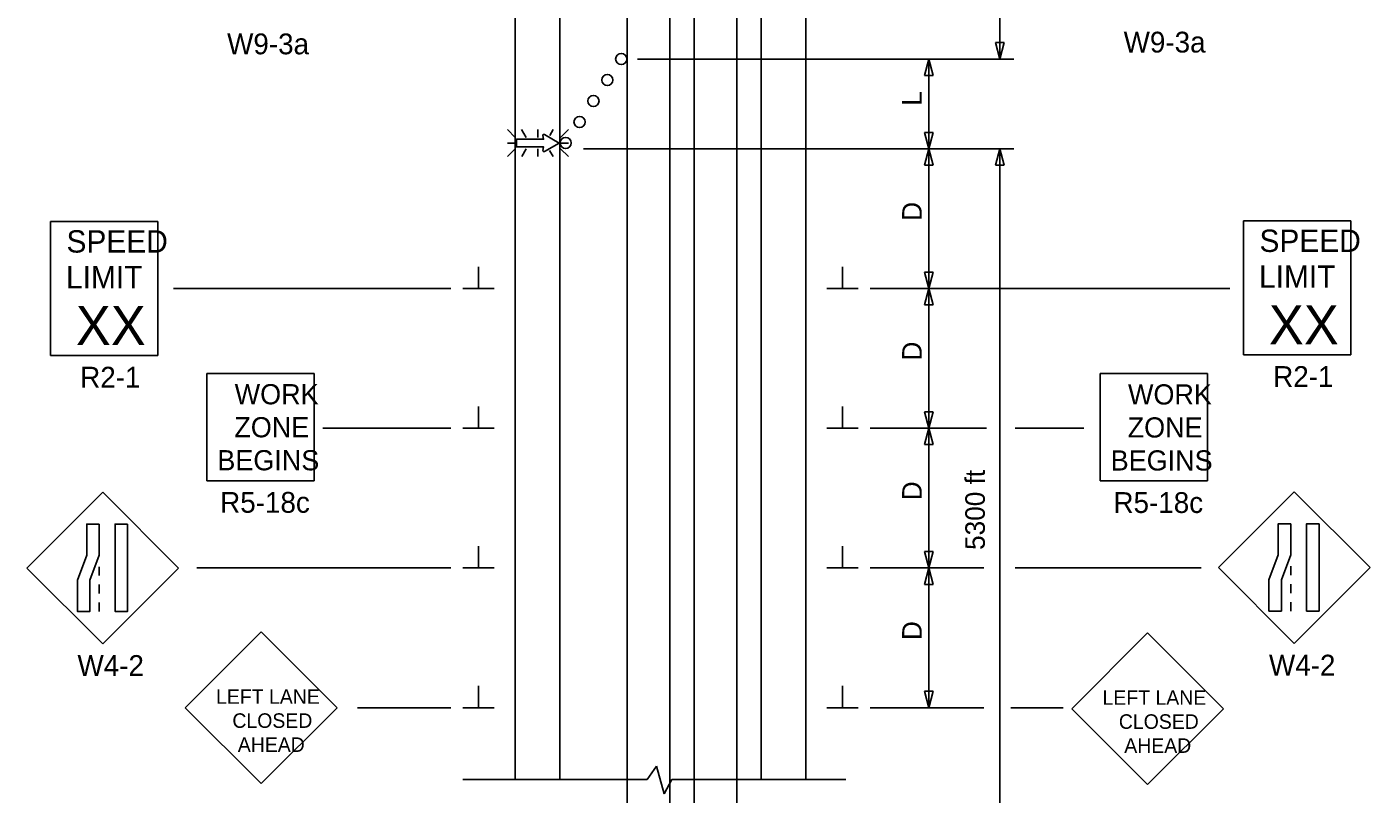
# Model space of a CAD drawing. Extents: x 16450 to 18482, y 7002 to 8333.
# Drawn here: x 16766 to 17246.6, y 7557.2 to 7831.7 of the extents above; entities that cross this region are included whole.
import ezdxf

# ---------------------------------------------------------------- set-up
doc = ezdxf.new("R2010")
doc.units = 0
for name, color, linetype in [('ALI_LEGAL_EX', 7, 'Continuous'), ('PAVT_EDGE_EX', 7, 'Continuous'), ('TRAFFIC_SIGNS_PR', 7, 'Continuous'), ('TYPICAL_TEXT_DIMEN_PR', 7, 'Continuous')]:
    doc.layers.add(name, color=color, linetype=linetype)

msp = doc.modelspace()

# ---------------------------------------------------------------- linework, layer by layer
at = {"layer": 'ALI_LEGAL_EX'}
for p, q in [((16980.68, 8333.08), (16980.68, 7514.94)), ((17004.68, 8333.08), (17004.68, 7514.94)), ((16995.95, 8258.85), (16995.95, 7440.72)), ((17019.95, 8258.85), (17019.95, 7440.72)), ((16980.68, 7589.94), (16980.68, 8211.08)), ((17004.68, 7589.94), (17004.68, 8211.08))]:
    msp.add_line(p, q, dxfattribs=at)
for points in [[(16980.68, 7744.94), (16980.68, 7769.94)], [(17004.68, 7744.94), (17004.68, 7769.94)], [(16980.68, 7612.44), (16980.68, 7637.44)], [(17004.68, 7612.44), (17004.68, 7637.44)]]:
    msp.add_lwpolyline(points, dxfattribs=at)
at = {"layer": 'PAVT_EDGE_EX'}
for p, q in [((16940.68, 8211.52), (16940.68, 7562.44)), ((16956.68, 8211.52), (16956.68, 7562.44)), ((17028.68, 8211.52), (17028.68, 7562.44)), ((17044.68, 8211.52), (17044.68, 7562.44))]:
    msp.add_line(p, q, dxfattribs=at)
at = {"layer": 'TRAFFIC_SIGNS_PR'}
for p, q in [((16940.7, 7792.16), (16937.88, 7794.99)), ((16942.99, 7794.98), (16944.62, 7792.16)), ((16948.78, 7792.16), (16948.78, 7794.98)), ((16954.25, 7794.98), (16953.04, 7792.89)), ((16959.69, 7794.98), (16956.87, 7792.16)), ((16940.7, 7790.13), (16937.88, 7790.13)), ((16940.7, 7788.1), (16937.88, 7785.28)), ((16944.65, 7788.1), (16943.02, 7785.28)), ((16948.78, 7788.1), (16948.78, 7785.28)), ((16952.96, 7787.47), (16954.22, 7785.28)), ((16956.87, 7790.13), (16959.69, 7790.13)), ((16959.69, 7785.28), (16956.87, 7788.1)), ((16774.36, 7762.08), (16812.76, 7762.08)), ((16774.36, 7714.08), (16774.36, 7762.08)), ((16812.76, 7714.08), (16812.76, 7762.08)), ((17201.21, 7762.31), (17239.61, 7762.31)), ((17201.21, 7714.31), (17201.21, 7762.31)), ((17239.61, 7714.31), (17239.61, 7762.31)), ((16774.36, 7714.08), (16812.76, 7714.08)), ((17201.21, 7714.31), (17239.61, 7714.31)), ((16830.31, 7669.29), (16830.31, 7707.69)), ((16830.31, 7707.69), (16868.71, 7707.69)), ((16868.71, 7669.29), (16868.71, 7707.69)), ((17149.93, 7669.22), (17149.93, 7707.62)), ((17149.93, 7707.62), (17188.33, 7707.62)), ((17188.33, 7669.22), (17188.33, 7707.62)), ((16830.31, 7669.29), (16868.71, 7669.29)), ((17149.93, 7669.22), (17188.33, 7669.22)), ((16793.11, 7665.22), (16765.96, 7638.06)), ((16820.26, 7638.06), (16793.11, 7665.22)), ((17219.41, 7665.36), (17192.26, 7638.21)), ((17246.57, 7638.21), (17219.41, 7665.36)), ((16765.96, 7638.06), (16793.11, 7610.91)), ((16791.86, 7638.56), (16791.86, 7635.36)), ((16793.11, 7610.91), (16820.26, 7638.06)), ((17192.26, 7638.21), (17219.41, 7611.05)), ((17218.17, 7638.7), (17218.17, 7635.5)), ((17219.41, 7611.05), (17246.57, 7638.21)), ((16791.86, 7632.16), (16791.86, 7628.96)), ((17218.17, 7632.3), (17218.17, 7629.1)), ((16791.86, 7625.76), (16791.86, 7622.56)), ((17218.17, 7625.9), (17218.17, 7622.7)), ((16849.78, 7615.25), (16822.62, 7588.09)), ((16876.93, 7588.09), (16849.78, 7615.25)), ((17166.95, 7614.9), (17139.79, 7587.74)), ((17194.1, 7587.74), (17166.95, 7614.9)), ((16822.62, 7588.09), (16849.78, 7560.94)), ((16849.78, 7560.94), (16876.93, 7588.09)), ((17139.79, 7587.74), (17166.95, 7560.59)), ((17166.95, 7560.59), (17194.1, 7587.74))]:
    msp.add_line(p, q, dxfattribs=at)
for points in [[(16950.61, 7792.81), (16950.84, 7791.52), (16941.12, 7791.52), (16941.12, 7788.77), (16950.84, 7788.77), (16950.61, 7787.47)], [(16951.11, 7787.12), (16956.42, 7790.13), (16951.11, 7793.17)]]:
    msp.add_lwpolyline(points, dxfattribs=at)
for points in [[(16791.86, 7653.8), (16791.86, 7642.62), (16788.52, 7633.74), (16788.52, 7622.56), (16784.02, 7622.56), (16784.02, 7633.74), (16787.37, 7642.62), (16787.37, 7653.8)], [(16802, 7653.8), (16802, 7622.56), (16797.51, 7622.56), (16797.51, 7653.8)], [(17218.17, 7653.94), (17218.17, 7642.76), (17214.82, 7633.88), (17214.82, 7622.7), (17210.33, 7622.7), (17210.33, 7633.88), (17213.67, 7642.76), (17213.67, 7653.94)], [(17228.3, 7653.94), (17228.3, 7622.7), (17223.81, 7622.7), (17223.81, 7653.94)]]:
    msp.add_lwpolyline(points, close=True, dxfattribs=at)
for centre in [(16978.61, 7820.2), (16973.65, 7812.69), (16968.68, 7805.18), (16963.71, 7797.68), (16958.74, 7790.17)]:
    msp.add_circle(centre, 2, dxfattribs=at)
for centre, start, end in [((16950.94, 7792.87), 61.4833, 189.9593), ((16950.94, 7787.42), 170.7308, 298.8916)]:
    msp.add_arc(centre, 0.341, start, end, dxfattribs=at)
at = {"layer": 'TYPICAL_TEXT_DIMEN_PR'}
for p, q in [((17114.11, 7938.07), (17114.11, 7820.2)), ((17114.11, 7820.2), (17112.54, 7826.06)), ((17112.54, 7826.06), (17114.11, 7826.06)), ((17114.11, 7826.06), (17115.68, 7826.06)), ((17115.68, 7826.06), (17114.11, 7820.2)), ((16984.43, 7820.2), (17093.68, 7820.2)), ((16984.43, 7820.2), (17119.11, 7820.2)), ((17087.11, 7814.34), (17088.68, 7820.2)), ((17088.68, 7820.2), (17088.68, 7788.09)), ((17088.68, 7820.2), (17090.25, 7814.34)), ((17088.68, 7814.34), (17087.11, 7814.34)), ((17090.25, 7814.34), (17088.68, 7814.34)), ((17088.68, 7788.09), (17087.11, 7793.96)), ((17087.11, 7793.96), (17088.68, 7793.96)), ((17088.68, 7793.96), (17090.25, 7793.96)), ((17090.25, 7793.96), (17088.68, 7788.09)), ((16965.08, 7788.09), (17093.68, 7788.09)), ((17119.11, 7788.09), (17047.98, 7788.09)), ((17087.11, 7782.23), (17088.68, 7788.09)), ((17088.68, 7788.09), (17088.68, 7738.09)), ((17088.68, 7788.09), (17090.25, 7782.23)), ((17112.54, 7782.23), (17114.11, 7788.09)), ((17114.11, 7788.09), (17115.68, 7782.23)), ((17114.11, 7788.09), (17114.11, 7505.59)), ((17088.68, 7782.23), (17087.11, 7782.23)), ((17090.25, 7782.23), (17088.68, 7782.23)), ((17114.11, 7782.23), (17112.54, 7782.23)), ((17115.68, 7782.23), (17114.11, 7782.23)), ((16927.55, 7738.09), (16927.55, 7745.88)), ((16927.55, 7738.09), (16927.55, 7745.88)), ((17057.8, 7738.09), (17057.8, 7745.88)), ((17088.68, 7738.09), (17087.11, 7743.96)), ((17087.11, 7743.96), (17088.68, 7743.96)), ((17088.68, 7743.96), (17090.25, 7743.96)), ((17090.25, 7743.96), (17088.68, 7738.09)), ((16818.41, 7738.09), (16917.68, 7738.09)), ((16891.68, 7738.09), (16917.68, 7738.09)), ((16921.93, 7738.09), (16933.18, 7738.09)), ((16921.93, 7738.09), (16933.18, 7738.09)), ((17063.43, 7738.09), (17052.18, 7738.09)), ((17196.38, 7738.09), (17067.68, 7738.09)), ((17087.11, 7732.23), (17088.68, 7738.09)), ((17088.68, 7738.09), (17088.68, 7688.09)), ((17088.68, 7738.09), (17090.25, 7732.23)), ((17088.68, 7732.23), (17087.11, 7732.23)), ((17090.25, 7732.23), (17088.68, 7732.23)), ((16927.55, 7688.09), (16927.55, 7695.88)), ((16927.55, 7688.09), (16927.55, 7695.88)), ((17057.8, 7688.09), (17057.8, 7695.88)), ((17088.68, 7688.09), (17087.11, 7693.96)), ((17087.11, 7693.96), (17088.68, 7693.96)), ((17088.68, 7693.96), (17090.25, 7693.96)), ((17090.25, 7693.96), (17088.68, 7688.09)), ((16871.81, 7688.09), (16917.68, 7688.09)), ((16891.68, 7688.09), (16917.68, 7688.09)), ((16921.93, 7688.09), (16933.18, 7688.09)), ((16921.93, 7688.09), (16933.18, 7688.09)), ((17063.43, 7688.09), (17052.18, 7688.09)), ((17109.32, 7688.09), (17067.68, 7688.09)), ((17087.11, 7682.23), (17088.68, 7688.09)), ((17088.68, 7688.09), (17088.68, 7638.09)), ((17088.68, 7688.09), (17090.25, 7682.23)), ((17144.1, 7688.09), (17119.6, 7688.09)), ((17088.68, 7682.23), (17087.11, 7682.23)), ((17090.25, 7682.23), (17088.68, 7682.23)), ((16927.55, 7638.09), (16927.55, 7645.88)), ((16927.55, 7638.09), (16927.55, 7645.88)), ((17057.8, 7638.09), (17057.8, 7645.88)), ((17088.68, 7638.09), (17087.11, 7643.96)), ((17087.11, 7643.96), (17088.68, 7643.96)), ((17088.68, 7643.96), (17090.25, 7643.96)), ((17090.25, 7643.96), (17088.68, 7638.09)), ((16826.73, 7638.09), (16917.68, 7638.09)), ((16891.68, 7638.09), (16917.68, 7638.09)), ((16921.93, 7638.09), (16933.18, 7638.09)), ((16921.93, 7638.09), (16933.18, 7638.09)), ((17063.43, 7638.09), (17052.18, 7638.09)), ((17108.3, 7638.09), (17067.68, 7638.09)), ((17087.11, 7632.23), (17088.68, 7638.09)), ((17088.68, 7638.09), (17088.68, 7588.09)), ((17088.68, 7638.09), (17090.25, 7632.23)), ((17186.06, 7638.09), (17119.6, 7638.09)), ((17088.68, 7632.23), (17087.11, 7632.23)), ((17090.25, 7632.23), (17088.68, 7632.23)), ((16927.55, 7588.09), (16927.55, 7595.88)), ((17057.8, 7588.09), (17057.8, 7595.88)), ((17088.68, 7588.09), (17087.11, 7593.96)), ((17087.11, 7593.96), (17088.68, 7593.96)), ((17088.68, 7593.96), (17090.25, 7593.96)), ((17090.25, 7593.96), (17088.68, 7588.09)), ((16884.28, 7588.09), (16917.68, 7588.09)), ((16921.93, 7588.09), (16933.18, 7588.09)), ((17063.43, 7588.09), (17052.18, 7588.09)), ((17108.3, 7588.09), (17067.68, 7588.09)), ((17136.76, 7588.09), (17118.06, 7588.09)), ((16991.19, 7567.24), (16987.94, 7562.44)), ((16993.93, 7557.3), (16991.19, 7567.24)), ((16987.94, 7562.44), (16921.99, 7562.44)), ((16996.67, 7562.44), (16993.93, 7557.3)), ((17059.01, 7562.44), (16996.67, 7562.44))]:
    msp.add_line(p, q, dxfattribs=at)

# ---------------------------------------------------------------- texts
at = {"layer": 'TRAFFIC_SIGNS_PR'}
for s, height, p in [('W9-3a', 7.44, (16837.61, 7821.89)), ('W9-3a', 7.44, (17158.38, 7822.52)), ('SPEED', 8, (16780.13, 7750.94)), ('SPEED', 8, (17206.97, 7751.17)), ('LIMIT', 8, (16779.97, 7738.14)), ('LIMIT', 8, (17206.81, 7738.37)), ('XX', 14.031, (16783.47, 7717.83)), ('XX', 14.031, (17210.32, 7718.07)), ('R2-1', 7.44, (16785.04, 7702.64)), ('R2-1', 7.44, (17211.88, 7702.87)), ('WORK', 7.217, (16840.31, 7696.66)), ('WORK', 7.217, (17159.93, 7696.59)), ('ZONE', 7.217, (16840.19, 7684.85)), ('ZONE', 7.217, (17159.81, 7684.78)), ('BEGINS', 7.217, (16834.11, 7673.04)), ('BEGINS', 7.217, (17153.74, 7672.97)), ('R5-18c', 7.44, (16835.12, 7657.85)), ('R5-18c', 7.44, (17154.74, 7657.78)), ('W4-2', 7.44, (16784.07, 7599.47)), ('W4-2', 7.44, (17210.37, 7599.61)), ('LEFT LANE', 5.2, (16833.66, 7589.49)), ('LEFT LANE', 5.2, (17150.83, 7589.14)), ('CLOSED', 5.2, (16839.49, 7580.89)), ('CLOSED', 5.2, (17156.66, 7580.54)), ('AHEAD', 5.2, (16841.43, 7572.29)), ('AHEAD', 5.2, (17158.6, 7571.94))]:
    msp.add_text(s, height=height, dxfattribs=at).set_placement(p)
at = {"layer": 'TYPICAL_TEXT_DIMEN_PR'}
for s, p in [('L', (17086.12, 7803.5)), ('D', (17086.12, 7762.31)), ('D', (17086.12, 7712.31)), ('5300 ft', (17108.72, 7644.56)), ('D', (17086.12, 7662.31)), ('D', (17086.12, 7612.31))]:
    msp.add_text(s, height=7, rotation=90, dxfattribs=at).set_placement(p)

doc.saveas('drawing.dxf')
